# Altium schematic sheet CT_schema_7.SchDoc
size 366 x 243 mm
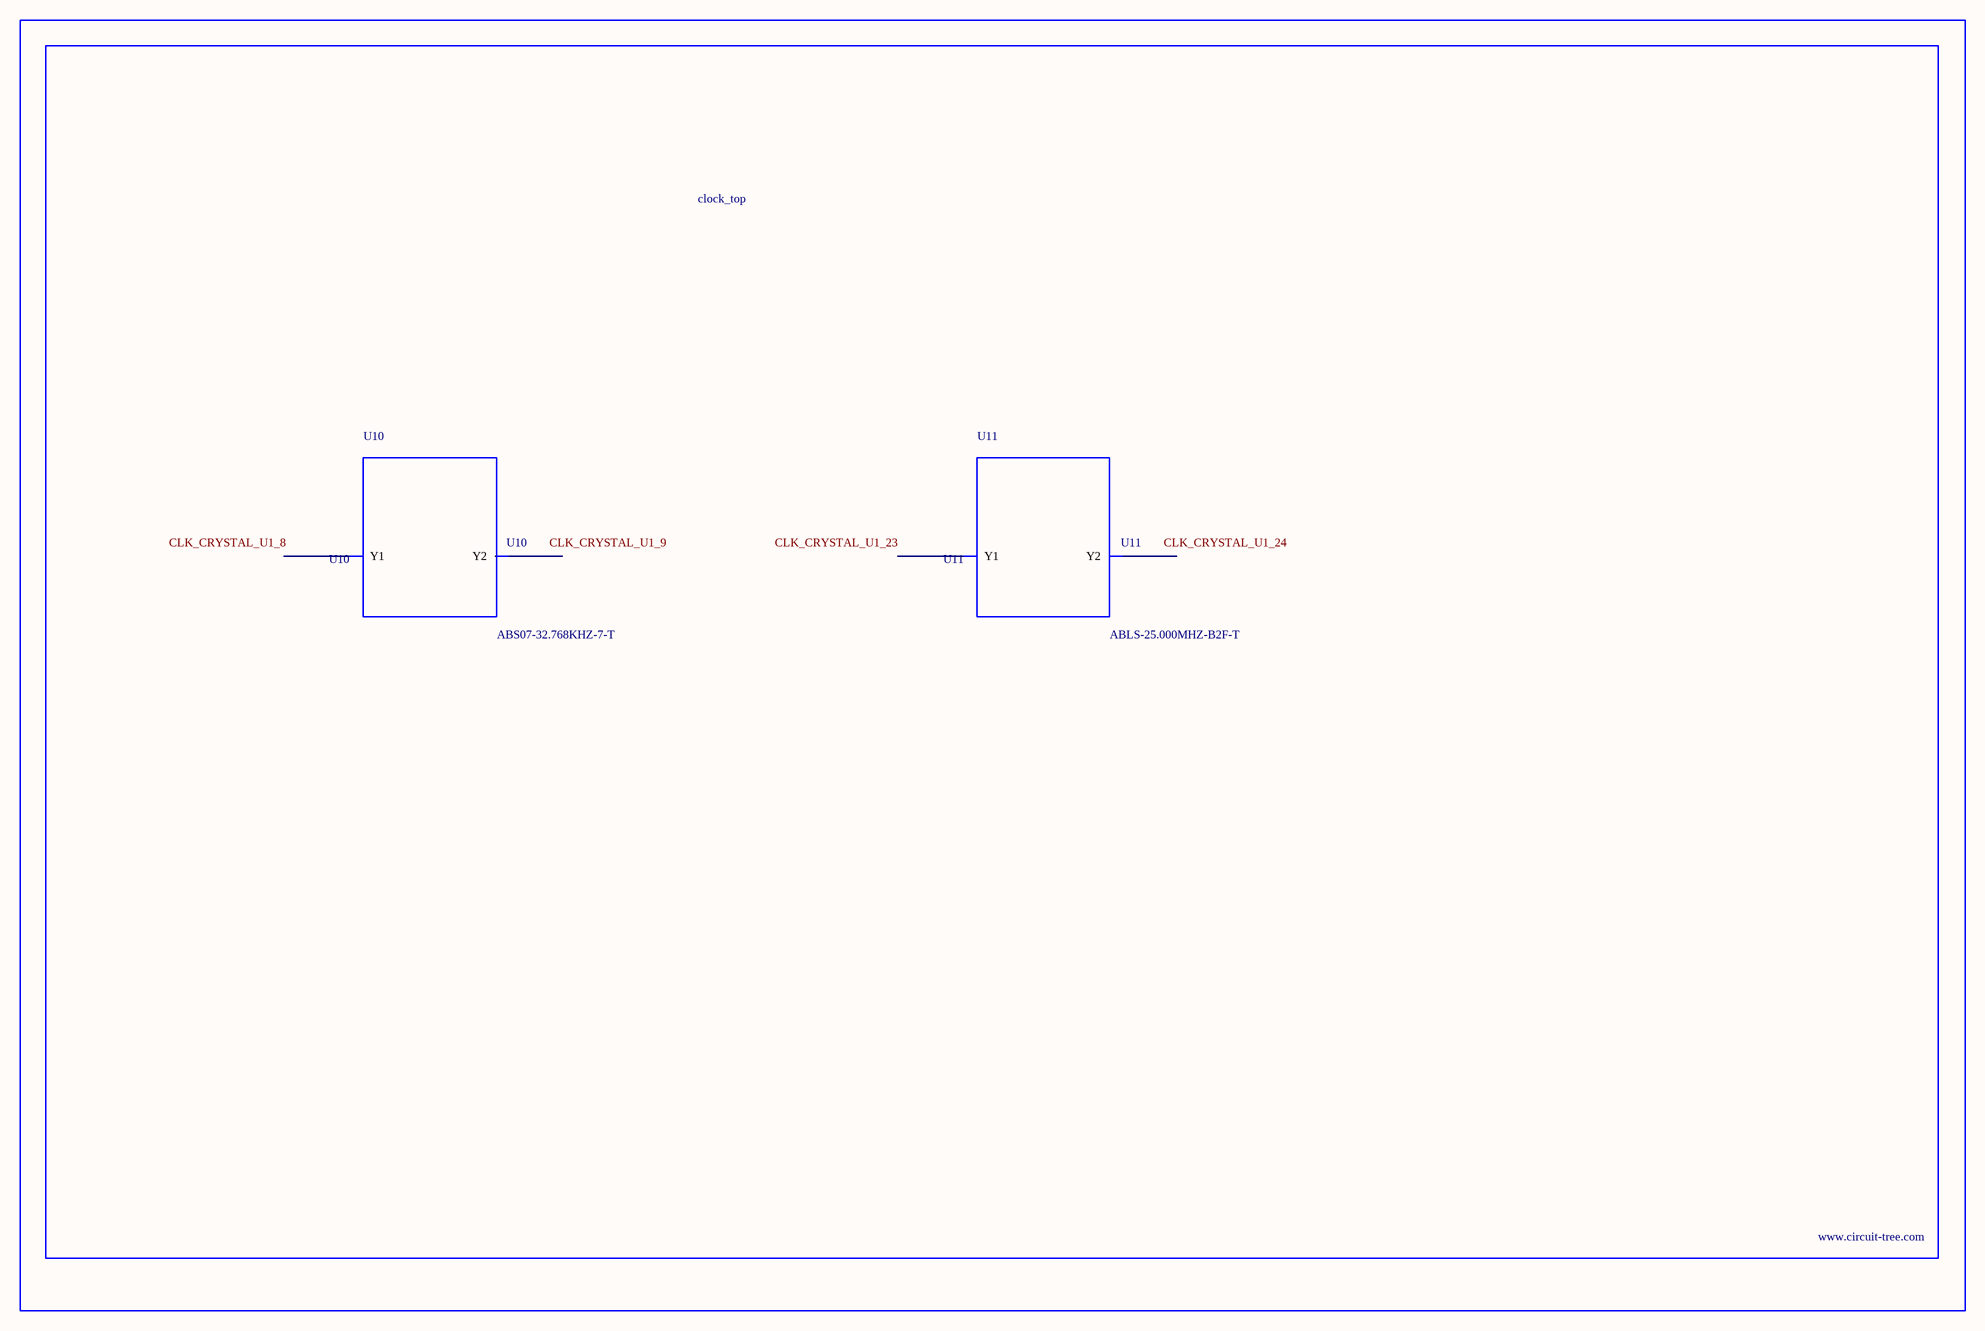
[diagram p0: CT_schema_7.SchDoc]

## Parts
BORDER6  (no value)
U10  ABS07-32.768KHZ-7-T  [ABS07-32.768KHZ-7-T]
U11  ABLS-25.000MHZ-B2F-T  [ABLS-25.000MHZ-B2F-T]

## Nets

Not connected (* = marked no-connect by the designer): U10 1(Y1) 2(Y2); U11 1(Y1) 2(Y2)

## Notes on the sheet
- Labels drawn without touching a wire or pin: CLK_CRYSTAL_U1_8, CLK_CRYSTAL_U1_9, CLK_CRYSTAL_U1_23, CLK_CRYSTAL_U1_24

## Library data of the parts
BORDER6 = BORDER_PAGE6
